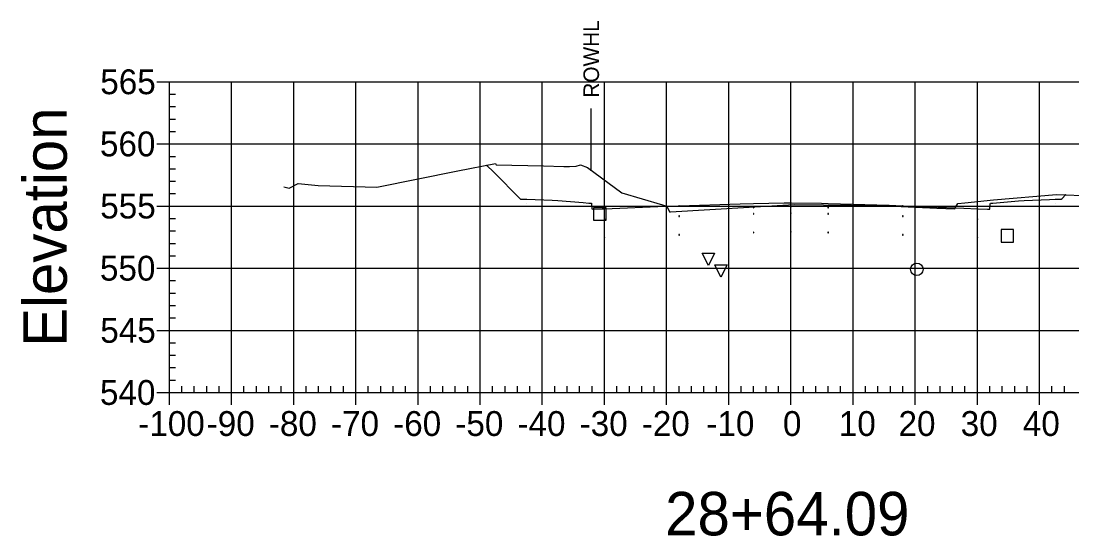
# Model space of a CAD drawing. Extents: x 708103 to 717568, y 374476 to 378707.
# Drawn here: x 710028.1 to 710197.2, y 377871.5 to 377954.4 of the extents above; entities that cross this region are included whole.
import ezdxf

# ---------------------------------------------------------------- set-up
doc = ezdxf.new("R2010")
doc.units = 0
for name, color, linetype in [('1', 7, 'Continuous'), ('10', 7, 'Continuous'), ('13', 7, 'Continuous'), ('14', 7, 'Continuous'), ('22', 7, 'Continuous'), ('4', 7, 'Continuous'), ('57', 7, 'Continuous'), ('60', 7, 'Continuous'), ('Existing', 7, 'Continuous'), ('XS_Right_of_Way', 7, 'Continuous')]:
    doc.layers.add(name, color=color, linetype=linetype)

msp = doc.modelspace()

# ---------------------------------------------------------------- linework, layer by layer
for points in [[(710133.93, 377922.97), (710134.03, 377922.97), (710134.03, 377923.07), (710133.93, 377923.07)], [(710145.93, 377924.33), (710146.03, 377924.33), (710146.03, 377924.43), (710145.93, 377924.43)], [(710145.93, 377923.33), (710146.03, 377923.33), (710146.03, 377923.43), (710145.93, 377923.43)], [(710151.93, 377924.45), (710152.03, 377924.45), (710152.03, 377924.55), (710151.93, 377924.55)], [(710151.93, 377923.45), (710152.03, 377923.45), (710152.03, 377923.55), (710151.93, 377923.55)], [(710157.93, 377924.33), (710158.03, 377924.33), (710158.03, 377924.43), (710157.93, 377924.43)], [(710157.93, 377923.33), (710158.03, 377923.33), (710158.03, 377923.43), (710157.93, 377923.43)], [(710169.93, 377922.97), (710170.03, 377922.97), (710170.03, 377923.07), (710169.93, 377923.07)], [(710121.93, 377922.49), (710122.03, 377922.49), (710122.03, 377922.59), (710121.93, 377922.59)], [(710181.93, 377922.49), (710182.03, 377922.49), (710182.03, 377922.59), (710181.93, 377922.59)], [(710121.93, 377919.49), (710122.03, 377919.49), (710122.03, 377919.59), (710121.93, 377919.59)], [(710133.93, 377919.97), (710134.03, 377919.97), (710134.03, 377920.07), (710133.93, 377920.07)], [(710145.93, 377920.33), (710146.03, 377920.33), (710146.03, 377920.43), (710145.93, 377920.43)], [(710151.93, 377920.45), (710152.03, 377920.45), (710152.03, 377920.55), (710151.93, 377920.55)], [(710157.93, 377920.33), (710158.03, 377920.33), (710158.03, 377920.43), (710157.93, 377920.43)], [(710169.93, 377919.97), (710170.03, 377919.97), (710170.03, 377920.07), (710169.93, 377920.07)], [(710181.93, 377919.49), (710182.03, 377919.49), (710182.03, 377919.59), (710181.93, 377919.59)]]:
    msp.add_lwpolyline(points, close=True)
at = {"layer": '1'}
for points in [[(710138.7, 377915.07), (710137.7, 377917.07), (710139.7, 377917.07)], [(710140.71, 377913.19), (710139.71, 377915.19), (710141.71, 377915.19)]]:
    msp.add_lwpolyline(points, close=True, dxfattribs=at)
at = {"layer": '10'}
msp.add_lwpolyline([(710120.23, 377922.37), (710122.23, 377922.37), (710122.23, 377924.37), (710120.23, 377924.37)], close=True, dxfattribs=at)
at = {"layer": '13'}
msp.add_circle((710172.23, 377914.45), 1, dxfattribs=at)
at = {"layer": '14'}
for points in [[(710103.07, 377931.18), (710103.07, 377931.23), (710103.07, 377931.18), (710103.02, 377931.18), (710103.07, 377931.18), (710103.07, 377931.13), (710103.07, 377931.18), (710103.12, 377931.18)], [(710196.17, 377926.45), (710196.17, 377926.5), (710196.17, 377926.45), (710196.12, 377926.45), (710196.17, 377926.45), (710196.17, 377926.4), (710196.17, 377926.45), (710196.22, 377926.45)], [(710133.98, 377924.68), (710133.98, 377924.73), (710133.98, 377924.68), (710133.93, 377924.68), (710133.98, 377924.68), (710133.98, 377924.63), (710133.98, 377924.68), (710134.03, 377924.68)], [(710151.98, 377925.16), (710151.98, 377925.21), (710151.98, 377925.16), (710151.93, 377925.16), (710151.98, 377925.16), (710151.98, 377925.11), (710151.98, 377925.16), (710152.03, 377925.16)], [(710169.98, 377924.68), (710169.98, 377924.73), (710169.98, 377924.68), (710169.93, 377924.68), (710169.98, 377924.68), (710169.98, 377924.63), (710169.98, 377924.68), (710170.03, 377924.68)], [(710121.98, 377924.2), (710121.98, 377924.25), (710121.98, 377924.2), (710121.93, 377924.2), (710121.98, 377924.2), (710121.98, 377924.15), (710121.98, 377924.2), (710122.03, 377924.2)], [(710181.98, 377924.2), (710181.98, 377924.25), (710181.98, 377924.2), (710181.93, 377924.2), (710181.98, 377924.2), (710181.98, 377924.15), (710181.98, 377924.2), (710182.03, 377924.2)]]:
    msp.add_lwpolyline(points, dxfattribs=at)
at = {"layer": '22'}
msp.add_lwpolyline([(710103.07, 377931.18), (710104.11, 377930.14), (710108.48, 377925.76), (710109.3, 377925.73), (710109.48, 377925.72), (710113.57, 377925.56), (710114.48, 377925.52), (710118.57, 377925.2), (710119.48, 377925.12), (710119.83, 377925.12), (710119.9, 377925.12), (710119.97, 377924.31), (710119.98, 377924.12), (710121.62, 377924.19), (710121.98, 377924.2), (710131.8, 377924.6), (710133.98, 377924.68), (710143.8, 377924.98), (710145.98, 377925.04), (710150.89, 377925.14), (710151.98, 377925.16), (710156.89, 377925.07), (710157.98, 377925.04), (710167.8, 377924.75), (710169.98, 377924.68), (710179.81, 377924.29), (710181.98, 377924.2), (710183.62, 377924.14), (710183.98, 377924.12), (710184.05, 377924.94), (710184.07, 377925.12), (710184.41, 377925.12), (710184.48, 377925.12), (710188.58, 377925.45), (710189.48, 377925.52), (710193.58, 377925.69), (710194.48, 377925.72), (710195.3, 377925.76), (710195.48, 377925.76), (710195.59, 377925.87), (710196.17, 377926.45)], dxfattribs=at)
at = {"layer": '4'}
msp.add_lwpolyline([(710185.78, 377918.84), (710187.78, 377918.84), (710187.78, 377920.84), (710185.78, 377920.84)], close=True, dxfattribs=at)
at = {"layer": '57'}
for p, q in [((710049.98, 377944.63), (710051.98, 377944.63)), ((710051.98, 377944.63), (710251.98, 377944.63)), ((710051.98, 377894.63), (710051.98, 377944.63)), ((710051.98, 377894.63), (710051.98, 377944.63)), ((710061.98, 377894.63), (710061.98, 377944.63)), ((710071.98, 377894.63), (710071.98, 377944.63)), ((710081.98, 377894.63), (710081.98, 377944.63)), ((710091.98, 377894.63), (710091.98, 377944.63)), ((710101.98, 377894.63), (710101.98, 377944.63)), ((710111.98, 377894.63), (710111.98, 377944.63)), ((710121.98, 377894.63), (710121.98, 377944.63)), ((710131.98, 377894.63), (710131.98, 377944.63)), ((710141.98, 377894.63), (710141.98, 377944.63)), ((710151.98, 377894.63), (710151.98, 377944.63)), ((710161.98, 377894.63), (710161.98, 377944.63)), ((710171.98, 377894.63), (710171.98, 377944.63)), ((710181.98, 377894.63), (710181.98, 377944.63)), ((710191.98, 377894.63), (710191.98, 377944.63)), ((710051.98, 377942.63), (710052.98, 377942.63)), ((710051.98, 377940.63), (710052.98, 377940.63)), ((710051.98, 377938.63), (710052.98, 377938.63)), ((710051.98, 377936.63), (710052.98, 377936.63)), ((710049.98, 377934.63), (710051.98, 377934.63)), ((710051.98, 377934.63), (710251.98, 377934.63)), ((710051.98, 377932.63), (710052.98, 377932.63)), ((710051.98, 377930.63), (710052.98, 377930.63)), ((710051.98, 377928.63), (710052.98, 377928.63)), ((710051.98, 377926.63), (710052.98, 377926.63)), ((710049.98, 377924.63), (710051.98, 377924.63)), ((710051.98, 377924.63), (710251.98, 377924.63)), ((710051.98, 377922.63), (710052.98, 377922.63)), ((710051.98, 377920.63), (710052.98, 377920.63)), ((710051.98, 377918.63), (710052.98, 377918.63)), ((710051.98, 377916.63), (710052.98, 377916.63)), ((710049.98, 377914.63), (710051.98, 377914.63)), ((710051.98, 377914.63), (710251.98, 377914.63)), ((710051.98, 377912.63), (710052.98, 377912.63)), ((710051.98, 377910.63), (710052.98, 377910.63)), ((710051.98, 377908.63), (710052.98, 377908.63)), ((710051.98, 377906.63), (710052.98, 377906.63)), ((710049.98, 377904.63), (710051.98, 377904.63)), ((710051.98, 377904.63), (710251.98, 377904.63)), ((710051.98, 377902.63), (710052.98, 377902.63)), ((710051.98, 377900.63), (710052.98, 377900.63)), ((710051.98, 377898.63), (710052.98, 377898.63)), ((710051.98, 377896.63), (710052.98, 377896.63)), ((710049.98, 377894.63), (710051.98, 377894.63)), ((710051.98, 377894.63), (710251.98, 377894.63)), ((710051.98, 377894.63), (710251.98, 377894.63)), ((710051.98, 377892.63), (710051.98, 377894.63)), ((710053.98, 377894.63), (710053.98, 377895.63)), ((710055.98, 377894.63), (710055.98, 377895.63)), ((710057.98, 377894.63), (710057.98, 377895.63)), ((710059.98, 377894.63), (710059.98, 377895.63)), ((710061.98, 377892.63), (710061.98, 377894.63)), ((710063.98, 377894.63), (710063.98, 377895.63)), ((710065.98, 377894.63), (710065.98, 377895.63)), ((710067.98, 377894.63), (710067.98, 377895.63)), ((710069.98, 377894.63), (710069.98, 377895.63)), ((710071.98, 377892.63), (710071.98, 377894.63)), ((710073.98, 377894.63), (710073.98, 377895.63)), ((710075.98, 377894.63), (710075.98, 377895.63)), ((710077.98, 377894.63), (710077.98, 377895.63)), ((710079.98, 377894.63), (710079.98, 377895.63)), ((710081.98, 377892.63), (710081.98, 377894.63)), ((710083.98, 377894.63), (710083.98, 377895.63)), ((710085.98, 377894.63), (710085.98, 377895.63)), ((710087.98, 377894.63), (710087.98, 377895.63)), ((710089.98, 377894.63), (710089.98, 377895.63)), ((710091.98, 377892.63), (710091.98, 377894.63)), ((710093.98, 377894.63), (710093.98, 377895.63)), ((710095.98, 377894.63), (710095.98, 377895.63)), ((710097.98, 377894.63), (710097.98, 377895.63)), ((710099.98, 377894.63), (710099.98, 377895.63)), ((710101.98, 377892.63), (710101.98, 377894.63)), ((710103.98, 377894.63), (710103.98, 377895.63)), ((710105.98, 377894.63), (710105.98, 377895.63)), ((710107.98, 377894.63), (710107.98, 377895.63)), ((710109.98, 377894.63), (710109.98, 377895.63)), ((710111.98, 377892.63), (710111.98, 377894.63)), ((710113.98, 377894.63), (710113.98, 377895.63)), ((710115.98, 377894.63), (710115.98, 377895.63)), ((710117.98, 377894.63), (710117.98, 377895.63)), ((710119.98, 377894.63), (710119.98, 377895.63)), ((710121.98, 377892.63), (710121.98, 377894.63)), ((710123.98, 377894.63), (710123.98, 377895.63)), ((710125.98, 377894.63), (710125.98, 377895.63)), ((710127.98, 377894.63), (710127.98, 377895.63)), ((710129.98, 377894.63), (710129.98, 377895.63)), ((710131.98, 377892.63), (710131.98, 377894.63)), ((710133.98, 377894.63), (710133.98, 377895.63)), ((710135.98, 377894.63), (710135.98, 377895.63)), ((710137.98, 377894.63), (710137.98, 377895.63)), ((710139.98, 377894.63), (710139.98, 377895.63)), ((710141.98, 377892.63), (710141.98, 377894.63)), ((710143.98, 377894.63), (710143.98, 377895.63)), ((710145.98, 377894.63), (710145.98, 377895.63)), ((710147.98, 377894.63), (710147.98, 377895.63)), ((710149.98, 377894.63), (710149.98, 377895.63)), ((710151.98, 377892.63), (710151.98, 377894.63)), ((710153.98, 377894.63), (710153.98, 377895.63)), ((710155.98, 377894.63), (710155.98, 377895.63)), ((710157.98, 377894.63), (710157.98, 377895.63)), ((710159.98, 377894.63), (710159.98, 377895.63)), ((710161.98, 377892.63), (710161.98, 377894.63)), ((710163.98, 377894.63), (710163.98, 377895.63)), ((710165.98, 377894.63), (710165.98, 377895.63)), ((710167.98, 377894.63), (710167.98, 377895.63)), ((710169.98, 377894.63), (710169.98, 377895.63)), ((710171.98, 377892.63), (710171.98, 377894.63)), ((710173.98, 377894.63), (710173.98, 377895.63)), ((710175.98, 377894.63), (710175.98, 377895.63)), ((710177.98, 377894.63), (710177.98, 377895.63)), ((710179.98, 377894.63), (710179.98, 377895.63)), ((710181.98, 377892.63), (710181.98, 377894.63)), ((710183.98, 377894.63), (710183.98, 377895.63)), ((710185.98, 377894.63), (710185.98, 377895.63)), ((710187.98, 377894.63), (710187.98, 377895.63)), ((710189.98, 377894.63), (710189.98, 377895.63)), ((710191.98, 377892.63), (710191.98, 377894.63)), ((710193.98, 377894.63), (710193.98, 377895.63)), ((710195.98, 377894.63), (710195.98, 377895.63))]:
    msp.add_line(p, q, dxfattribs=at)
at = {"layer": 'Existing'}
msp.add_lwpolyline([(710070.37, 377927.74), (710071.23, 377927.5), (710072.68, 377928.24), (710075.9, 377927.95), (710085.36, 377927.68), (710098.38, 377930.3), (710104.46, 377931.49), (710104.57, 377931.26), (710112.15, 377931.08), (710115.42, 377931.02), (710116.36, 377931.01), (710117.44, 377931.04), (710118.12, 377931.25), (710119.24, 377930.85), (710124.77, 377926.75), (710131.32, 377924.83), (710132.06, 377924.56), (710132.08, 377924.5), (710132.41, 377923.81), (710132.46, 377923.71), (710132.58, 377923.72), (710152.48, 377924.86), (710157.21, 377924.85), (710166.23, 377924.71), (710175.46, 377924.31), (710178.33, 377924.17), (710178.41, 377924.32), (710178.81, 377925.03), (710179.94, 377925.17), (710184.58, 377925.65), (710194.73, 377926.5), (710205.99, 377926.07)], dxfattribs=at)
at = {"layer": 'XS_Right_of_Way'}
msp.add_line((710119.78, 377940.32), (710119.78, 377930.32), dxfattribs=at)

# ---------------------------------------------------------------- texts
at = {"layer": '1'}
msp.add_text('28+64.09', height=7, dxfattribs=at).set_placement((710131.74, 377871.63))
at = {"layer": '14'}
for p in [(710109.45, 377925.67), (710109.45, 377925.01), (710114.45, 377924.81), (710189.45, 377924.81), (710194.45, 377925.67), (710194.45, 377925.01)]:
    msp.add_text('+', height=0.1, dxfattribs=at).set_placement(p)
at = {"layer": '57'}
for s, p in [('565', (710040.86, 377942.63)), ('560', (710040.81, 377932.63)), ('555', (710040.86, 377922.63)), ('550', (710040.81, 377912.63)), ('545', (710040.86, 377902.63)), ('540', (710040.81, 377892.63)), ('-100', (710046.97, 377887.63)), ('-90', (710057.98, 377887.63)), ('-80', (710067.98, 377887.63)), ('-70', (710077.98, 377887.63)), ('-60', (710087.98, 377887.63)), ('-50', (710097.98, 377887.63)), ('-40', (710107.98, 377887.63)), ('-30', (710117.98, 377887.63)), ('-20', (710127.98, 377887.63)), ('-10', (710138.37, 377887.63)), ('0', (710150.69, 377887.63)), ('10', (710159.68, 377887.63)), ('20', (710169.29, 377887.63)), ('30', (710179.29, 377887.63)), ('40', (710189.29, 377887.63))]:
    msp.add_text(s, height=4, dxfattribs=at).set_placement(p)
at = {"layer": '60'}
msp.add_text('Elevation', height=7, rotation=90, dxfattribs=at).set_placement((710035.48, 377901.99))
at = {"layer": 'XS_Right_of_Way'}
msp.add_text('ROWHL', height=2.5, rotation=90, dxfattribs=at).set_placement((710121.1, 377942.08))

doc.saveas('drawing.dxf')
